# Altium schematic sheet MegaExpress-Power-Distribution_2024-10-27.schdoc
size 137 x 87 mm
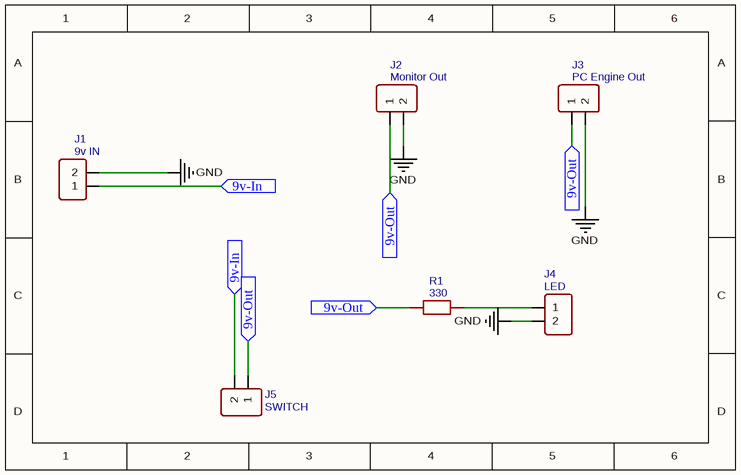
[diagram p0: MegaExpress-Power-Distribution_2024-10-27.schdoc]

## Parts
J1  9v IN  [HDR-M-2.54_1X2]
J2  Monitor Out  [HDR-M-2.54_1X2]
J3  PC Engine Out  [HDR-M-2.54_1X2]
J4  LED  [HDR-M-2.54_1X2]
J5  SWITCH  [HDR-M-2.54_1X2]
R1  330  [R0805]

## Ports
9v-In (in), 9v-Out (in)

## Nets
GND: J1.2 J2.2 J3.2 J4.2
9v-In: J1.1 J5.2 ; port 9v-In
9v-Out: J2.1 J3.1 J5.1 R1.1 ; port 9v-Out
NetJ4_1: J4.1 R1.2

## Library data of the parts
J1 = 9v IN: Contributor: LCEDA_Lib
J2 = Monitor Out: Contributor: LCEDA_Lib
J3 = PC Engine Out: Contributor: LCEDA_Lib
J4 = LED: Contributor: LCEDA_Lib
J5 = SWITCH: Contributor: LCEDA_Lib
R1 = 330: nameAlias: Value(Ω); Contributor: LCEDA_Lib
